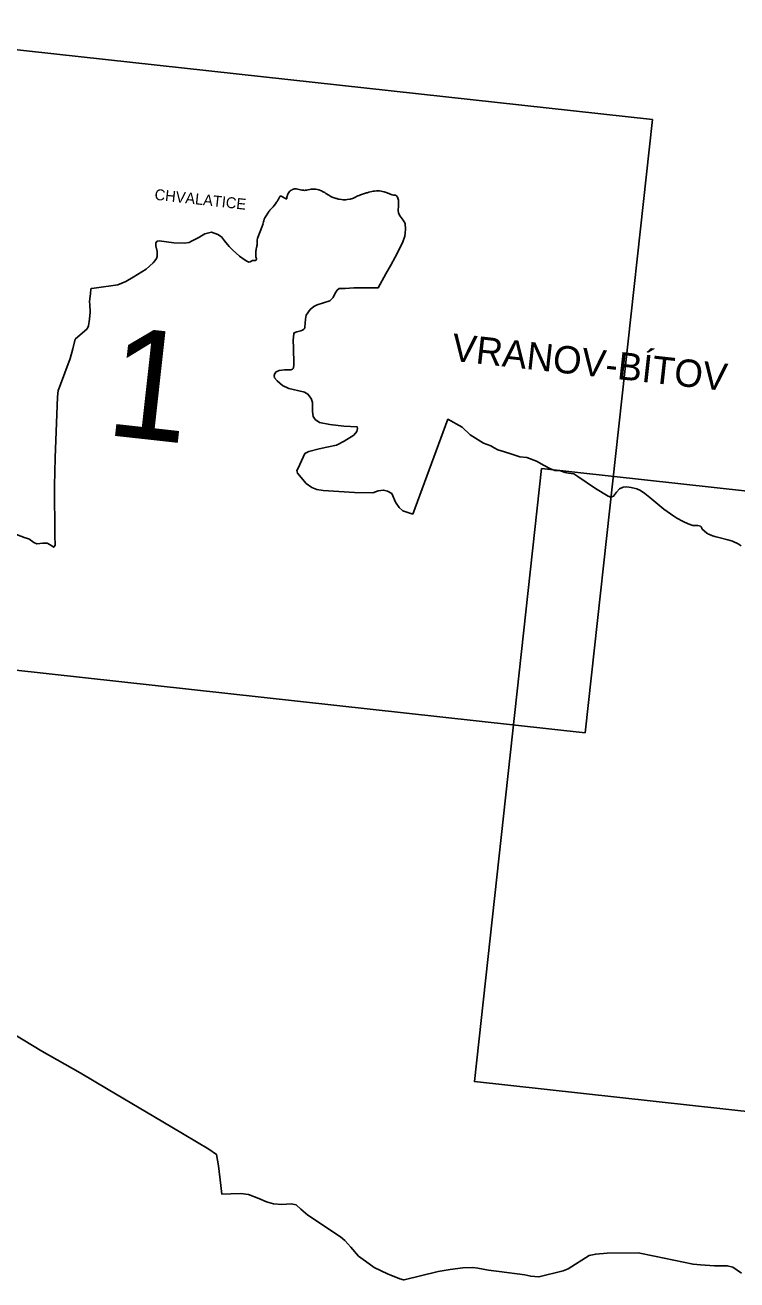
# Model space of a CAD drawing. Extents: x -678204 to -526855, y -1228851 to -1110393.
# Drawn here: x -663938 to -660037, y -1186114 to -1179242 of the extents above; entities that cross this region are included whole.
import ezdxf

# ---------------------------------------------------------------- set-up
doc = ezdxf.new("R2010")
doc.units = 0
for name, color, linetype in [('00_n_cyklo popisy detaily', 7, 'Continuous'), ('00_n_cyklo popisy ostatni', 7, 'Continuous'), ('00_n_cyklo prujezdne rekreacni hlavni', 7, 'Continuous'), ('00_n_cyklo prujezdne rekreacni vedlejsi', 7, 'Continuous'), ('00_n_cyklo studie rekreacni vedlejsi', 7, 'Continuous'), ('00_n_cyklo trasovani rekreacni hlavni', 7, 'Continuous'), ('00_n_cyklo trasovani rekreacni vedlejsi', 7, 'Continuous'), ('_HELP', 7, 'Continuous')]:
    doc.layers.add(name, color=color, linetype=linetype)

msp = doc.modelspace()

# ---------------------------------------------------------------- linework, layer by layer
at = {"layer": '00_n_cyklo prujezdne rekreacni hlavni'}
for points in [[(-664050.1, -1184736.6), (-663846.7, -1184860), (-663635.3, -1184980.1), (-663482.1, -1185070.9), (-663273, -1185195.5), (-663134.3, -1185277.8), (-662930.9, -1185398.4), (-662889.7, -1185426.6), (-662877.3, -1185489.2), (-662864.4, -1185596.3), (-662859.4, -1185644.8), (-662810.4, -1185642.9), (-662755, -1185640.9), (-662712.8, -1185645.5), (-662656.5, -1185667.7), (-662615.6, -1185686), (-662575.6, -1185697.3), (-662530.5, -1185700.2), (-662479.3, -1185697.6), (-662451.6, -1185702.8), (-662426.8, -1185727), (-662387.6, -1185758.2), (-662208.8, -1185878), (-662186, -1185898), (-662153.4, -1185935.1), (-662110, -1185984), (-662071.6, -1186010.5), (-662024.3, -1186045.2), (-661951.5, -1186079.4), (-661883.2, -1186107.1), (-661863.9, -1186113.5)], [(-661863.9, -1186113.5), (-661859.5, -1186112.5), (-661673.6, -1186068.1), (-661607.9, -1186056.2), (-661538, -1186047.5), (-661484.5, -1186046.5), (-661456.9, -1186048.5), (-661397.6, -1186059.7), (-661339.6, -1186067.5), (-661199.2, -1186085.5), (-661166.7, -1186093.9), (-661121.9, -1186097.5), (-660988.3, -1186063.7), (-660960.7, -1186052.4), (-660847.4, -1185980.2), (-660810.3, -1185972.3), (-660747.1, -1185967.2), (-660578.6, -1185966.1), (-660488.4, -1185983.6), (-660277.1, -1186028.1), (-660236.5, -1186031.5), (-660159.9, -1186036), (-660089.4, -1186036), (-660059.6, -1186043.4), (-660011.1, -1186077.2)]]:
    msp.add_lwpolyline(points, dxfattribs=at)
at = {"layer": '00_n_cyklo prujezdne rekreacni vedlejsi'}
for points in [[(-661812.1, -1181920.1), (-661867.4, -1181901.4), (-661887.9, -1181882.8), (-661907.9, -1181853.9), (-661927.1, -1181807.6), (-661951.6, -1181794.1), (-661973.4, -1181788.3), (-662002.3, -1181792.2), (-662031.9, -1181803.7), (-662132.8, -1181801.2), (-662305, -1181790.9), (-662338.4, -1181785.7), (-662366, -1181773.5), (-662396.9, -1181753), (-662444.4, -1181695.1), (-662448.3, -1181680.3), (-662440.6, -1181667.5), (-662403.9, -1181588.4), (-662382.1, -1181576.9), (-662325.5, -1181561.4), (-662283.8, -1181552.4), (-662231.7, -1181541.5), (-662188.7, -1181520.9), (-662135.3, -1181486.9), (-662119.9, -1181468.2), (-662115.4, -1181450.2), (-662118, -1181441.2), (-662190.6, -1181437.4), (-662267.1, -1181429), (-662324.3, -1181417.5), (-662347.4, -1181402.2), (-662359.6, -1181384.8), (-662363.5, -1181357.2), (-662362.2, -1181308.4), (-662369.2, -1181286.5), (-662387.9, -1181262.7), (-662407.1, -1181252.4), (-662413.6, -1181249.2), (-662493.3, -1181231.2), (-662528, -1181214.5), (-662556.9, -1181190.1), (-662570.1, -1181173), (-662572.3, -1181159.8), (-662569.4, -1181148.8), (-662562.4, -1181141.1), (-662545.5, -1181134.1), (-662516.8, -1181129.7), (-662482, -1181130), (-662472, -1181126.4), (-662467.6, -1181119.8), (-662465.1, -1181100.3), (-662466.3, -1181007), (-662469.2, -1180968.2), (-662467.4, -1180949.3), (-662465.9, -1180932.1), (-662462.5, -1180926.6), (-662449.5, -1180921.6), (-662426.2, -1180915.9), (-662418.1, -1180912.4), (-662411.1, -1180906.9), (-662404.4, -1180900.8), (-662404.2, -1180895.1), (-662401.6, -1180851.8), (-662396.8, -1180830.9), (-662374.8, -1180800), (-662355.3, -1180782.8), (-662336.6, -1180773.6), (-662268.2, -1180751), (-662249.6, -1180734.3), (-662238.7, -1180710.5), (-662227.8, -1180692.5), (-662216.5, -1180683.6), (-662183.1, -1180684.1), (-662136.8, -1180680.8), (-662015.9, -1180680.4), (-662002.7, -1180680.4), (-661960.4, -1180604), (-661933.8, -1180555.7), (-661910.5, -1180512.7), (-661869.5, -1180434.9), (-661856.6, -1180398.1), (-661854.3, -1180380.4), (-661853.7, -1180358.4), (-661854.8, -1180328.3), (-661866.1, -1180309.4), (-661883, -1180288.5), (-661892.1, -1180271.2), (-661893, -1180256.1), (-661891.8, -1180234), (-661892.1, -1180200.8), (-661897.5, -1180184.6), (-661901.5, -1180176.9), (-661905.7, -1180173.9)], [(-662692, -1180531.7), (-662695.8, -1180532.1), (-662704.2, -1180538.9), (-662710.9, -1180539.6), (-662722.5, -1180535.3), (-662742.3, -1180521), (-662762.3, -1180506.4), (-662797.2, -1180476.1), (-662818.6, -1180454.6), (-662844.7, -1180422.7), (-662862, -1180401.8), (-662881.6, -1180388.5), (-662915.5, -1180376.2), (-662952.5, -1180385.3), (-662990.2, -1180406.2), (-663025.2, -1180425.3), (-663039.2, -1180433), (-663066.2, -1180436.3), (-663123.1, -1180433.3), (-663202.6, -1180422.5), (-663214.1, -1180425.3), (-663221, -1180433.6), (-663220.7, -1180450.3), (-663214.3, -1180480.8), (-663213.8, -1180508.4), (-663217.7, -1180519.8), (-663226, -1180532.3), (-663236.3, -1180543.1), (-663274.2, -1180578.5), (-663346.4, -1180621.5), (-663385.8, -1180645.3), (-663429.2, -1180665), (-663558.9, -1180682.3), (-663575.7, -1180684.1), (-663578.3, -1180687.5), (-663579.8, -1180713.6), (-663583.8, -1180738.2), (-663585.2, -1180757.4), (-663583.1, -1180770.9), (-663581.2, -1180813.9), (-663585.3, -1180852.8), (-663590.2, -1180889.5), (-663598.1, -1180905.4), (-663663.1, -1180961.7), (-663675.9, -1181014.8), (-663691.2, -1181068), (-663749.4, -1181224.6), (-663755.8, -1181242), (-663759.7, -1181278), (-663772.3, -1181611.1), (-663776.6, -1181764.5), (-663774.6, -1182038.2), (-663773.9, -1182089), (-663780.5, -1182100.9), (-663801, -1182088.2), (-663816.7, -1182078.1), (-663840.3, -1182078.1), (-663874.1, -1182082.6), (-663889.8, -1182075.8), (-663916.8, -1182054.4), (-663937, -1182049.9), (-663985.4, -1182031.9)], [(-660227.8, -1182001.7), (-660228.5, -1181997), (-660231.8, -1181990.1), (-660236.9, -1181985), (-660251.1, -1181982.8), (-660278.6, -1181981.8), (-660303.7, -1181972.9), (-660330.7, -1181959.8), (-660366.2, -1181942.4), (-660382.8, -1181930.6), (-660436.6, -1181892.4), (-660513.4, -1181829.3), (-660540.8, -1181807.2), (-660564.6, -1181791), (-660586, -1181780.6), (-660615.9, -1181774.6), (-660639.2, -1181770.9), (-660660.3, -1181771.4), (-660680.2, -1181780.8), (-660696.9, -1181799), (-660712.6, -1181821.9), (-660728.2, -1181827.5), (-660743.2, -1181821.8), (-660812, -1181780.2), (-660909, -1181714), (-660930.9, -1181699.8), (-660959.8, -1181694.7), (-660977.5, -1181691.2), (-661003.4, -1181683.5), (-661035, -1181681.6), (-661061.9, -1181670.6), (-661093.2, -1181654), (-661134.4, -1181630), (-661188.3, -1181609.2), (-661226.5, -1181605.3), (-661271.2, -1181590.9), (-661311.2, -1181578.4), (-661347.4, -1181568), (-661367.3, -1181556.9), (-661384.5, -1181546.4), (-661425.8, -1181530.6), (-661498.1, -1181485.7), (-661543.1, -1181443.7), (-661620.8, -1181400.6), (-661812.1, -1181920.1)]]:
    msp.add_lwpolyline(points, dxfattribs=at)
at = {"layer": '00_n_cyklo studie rekreacni vedlejsi'}
for p, q in [((-662499.2, -1180170.4), (-662500.6, -1180174.2)), ((-662488.5, -1180153.7), (-662492.1, -1180158.1)), ((-662460.8, -1180138.5), (-662466.9, -1180140.1)), ((-662428.5, -1180143.5), (-662451.4, -1180138.4)), ((-662411.7, -1180146.3), (-662413.2, -1180146.1)), ((-662377.5, -1180141.5), (-662389.2, -1180144.6)), ((-662352, -1180140.1), (-662363.1, -1180139.8)), ((-662314.1, -1180149.5), (-662319.4, -1180147.2)), ((-662273.4, -1180173.6), (-662289, -1180163.1)), ((-662072.4, -1180162.7), (-662093.3, -1180169.5)), ((-662037.5, -1180153.2), (-662053.3, -1180157.2)), ((-662011.3, -1180149.5), (-662023.6, -1180150.8)), ((-661970.2, -1180155.3), (-661979.5, -1180152.5)), ((-661927, -1180170.8), (-661959.6, -1180158.8)), ((-661905.7, -1180173.9), (-661911.2, -1180173.8)), ((-662541, -1180180.7), (-662550.9, -1180197.8)), ((-662506.6, -1180193.4), (-662534.3, -1180178.8)), ((-662502.6, -1180183), (-662503.6, -1180191.9)), ((-662233.8, -1180190.7), (-662249.5, -1180185.4)), ((-662202.9, -1180196.9), (-662216.7, -1180194.9)), ((-662157, -1180194.3), (-662171.9, -1180196.8)), ((-662131.2, -1180185.4), (-662132.3, -1180186)), ((-662107.8, -1180174.8), (-662113.5, -1180177.1)), ((-662627, -1180304.6), (-662629.7, -1180313.5)), ((-662603.8, -1180265.8), (-662621, -1180291.8)), ((-662586.3, -1180245.1), (-662592.8, -1180251.9)), ((-662640.9, -1180348.9), (-662662.1, -1180404.9)), ((-662666.4, -1180433.9), (-662666.6, -1180441)), ((-662665.1, -1180417.9), (-662666, -1180427.1)), ((-662673.3, -1180487.3), (-662673.8, -1180504)), ((-662671.7, -1180516.3), (-662670, -1180520.4)), ((-662668.9, -1180459.8), (-662671, -1180469.1)), ((-662677.3, -1180531.4), (-662692, -1180531.7)), ((-660204.2, -1182021.9), (-660227.8, -1182001.7)), ((-660170.6, -1182038), (-660189.9, -1182030.4)), ((-660085.9, -1182060), (-660143.9, -1182046.3)), ((-660036.7, -1182078.8), (-660037.9, -1182078.2))]:
    msp.add_line(p, q, dxfattribs=at)
for centre, radius, start, end in [((-662462.9, -1180187.6), 40, 160.33333, 173.42013), ((-662461.5, -1180183.8), 40, 139.90308, 160.33333), ((-662457.9, -1180179.5), 40, 122.79014, 139.90308), ((-662456.8, -1180178.8), 40, 104.58657, 122.79014), ((-662455.7, -1180157.9), 20, 77.38567, 104.58657), ((-662395.7, -1179997.1), 150, 257.38567, 263.31699), ((-662404.8, -1180086.7), 60, 263.31699, 285.02658), ((-662364.5, -1180189.8), 50, 88.3446, 105.02658), ((-662354.6, -1180230.1), 90, 66.9806, 88.3446), ((-662372.7, -1180287.6), 150, 56.05492, 66.9806), ((-662217.5, -1180090.7), 100, 236.05492, 251.36339), ((-662031.7, -1180359.8), 200, 107.9257, 112.34408), ((-661980, -1180448.1), 300, 104.13058, 107.9257), ((-662013.1, -1180250.2), 100, 96.064, 104.13058), ((-662002.8, -1180229), 80, 73.08726, 96.064), ((-662028.3, -1180346.7), 200, 69.9027, 73.08726), ((-661909.8, -1180123.8), 50, 249.9027, 268.49392), ((-662767.4, -1180072.8), 250, 316.43223, 326.16198), ((-662767.2, -1180072.5), 250, 326.16198, 329.92449), ((-662536.6, -1180183.2), 5, 62.13845, 149.92449), ((-662505.6, -1180191.7), 2, 242.13845, 353.42013), ((-662201.8, -1180096), 100, 251.36339, 261.43582), ((-662188, -1180098.1), 100, 261.43582, 279.24776), ((-662169.8, -1180115.4), 80, 279.24776, 297.94511), ((-662037.5, -1180362.1), 200, 112.34408, 117.94511), ((-662579.2, -1180319.3), 50, 146.61999, 162.82175), ((-662520.3, -1180320.9), 100, 136.43223, 146.61999), ((-662874.7, -1180260.4), 250, 339.25816, 344.34226), ((-662152.1, -1180461.2), 500, 162.82175, 164.34226), ((-662766.6, -1180438.3), 100, 347.52881, 358.4293), ((-662566.4, -1180436.6), 100, 174.5327, 178.4293), ((-662615.3, -1180422.6), 50, 159.25816, 174.5327), ((-662643.9, -1180505), 30, 178.0284, 201.96177), ((-662573.3, -1180490.7), 100, 167.52881, 178.0284), ((-662677.4, -1180523.4), 8, 271.2676, 21.96177), ((-660171.7, -1181983.9), 50, 229.56013, 248.65897), ((-660097.8, -1181851.7), 200, 248.65897, 256.68492), ((-660132, -1182254.7), 200, 61.9425, 76.68492), ((-660130.8, -1182255.3), 200, 53.83808, 61.9425)]:
    msp.add_arc(centre, radius, start, end, dxfattribs=at)
at = {"layer": '00_n_cyklo trasovani rekreacni hlavni'}
for points in [[(-664050.1, -1184736.6), (-663846.7, -1184860), (-663635.3, -1184980.1), (-663482.1, -1185070.9), (-663273, -1185195.5), (-663134.3, -1185277.8), (-662930.9, -1185398.4), (-662889.7, -1185426.6), (-662877.3, -1185489.2), (-662864.4, -1185596.3), (-662859.4, -1185644.8), (-662810.4, -1185642.9), (-662755, -1185640.9), (-662712.8, -1185645.5), (-662656.5, -1185667.7), (-662615.6, -1185686), (-662575.6, -1185697.3), (-662530.5, -1185700.2), (-662479.3, -1185697.6), (-662451.6, -1185702.8), (-662426.8, -1185727), (-662387.6, -1185758.2), (-662208.8, -1185878), (-662186, -1185898), (-662153.4, -1185935.1), (-662110, -1185984), (-662071.6, -1186010.5), (-662024.3, -1186045.2), (-661951.5, -1186079.4), (-661883.2, -1186107.1), (-661863.9, -1186113.5)], [(-661863.9, -1186113.5), (-661859.5, -1186112.5), (-661673.6, -1186068.1), (-661607.9, -1186056.2), (-661538, -1186047.5), (-661484.5, -1186046.5), (-661456.9, -1186048.5), (-661397.6, -1186059.7), (-661339.6, -1186067.5), (-661199.2, -1186085.5), (-661166.7, -1186093.9), (-661121.9, -1186097.5), (-660988.3, -1186063.7), (-660960.7, -1186052.4), (-660847.4, -1185980.2), (-660810.3, -1185972.3), (-660747.1, -1185967.2), (-660578.6, -1185966.1), (-660488.4, -1185983.6), (-660277.1, -1186028.1), (-660236.5, -1186031.5), (-660159.9, -1186036), (-660089.4, -1186036), (-660059.6, -1186043.4), (-660011.1, -1186077.2)]]:
    msp.add_lwpolyline(points, dxfattribs=at)
at = {"layer": '00_n_cyklo trasovani rekreacni vedlejsi'}
for p, q in [((-662499.2, -1180170.4), (-662500.6, -1180174.2)), ((-662488.5, -1180153.7), (-662492.1, -1180158.1)), ((-662460.8, -1180138.5), (-662466.9, -1180140.1)), ((-662428.5, -1180143.5), (-662451.4, -1180138.4)), ((-662411.7, -1180146.3), (-662413.2, -1180146.1)), ((-662377.5, -1180141.5), (-662389.2, -1180144.6)), ((-662352, -1180140.1), (-662363.1, -1180139.8)), ((-662314.1, -1180149.5), (-662319.4, -1180147.2)), ((-662273.4, -1180173.6), (-662289, -1180163.1)), ((-662072.4, -1180162.7), (-662093.3, -1180169.5)), ((-662037.5, -1180153.2), (-662053.3, -1180157.2)), ((-662011.3, -1180149.5), (-662023.6, -1180150.8)), ((-661970.2, -1180155.3), (-661979.5, -1180152.5)), ((-661927, -1180170.8), (-661959.6, -1180158.8)), ((-661905.7, -1180173.9), (-661911.2, -1180173.8)), ((-662541, -1180180.7), (-662550.9, -1180197.8)), ((-662506.6, -1180193.4), (-662534.3, -1180178.8)), ((-662502.6, -1180183), (-662503.6, -1180191.9)), ((-662233.8, -1180190.7), (-662249.5, -1180185.4)), ((-662202.9, -1180196.9), (-662216.7, -1180194.9)), ((-662157, -1180194.3), (-662171.9, -1180196.8)), ((-662131.2, -1180185.4), (-662132.3, -1180186)), ((-662107.8, -1180174.8), (-662113.5, -1180177.1)), ((-662627, -1180304.6), (-662629.7, -1180313.5)), ((-662603.8, -1180265.8), (-662621, -1180291.8)), ((-662586.3, -1180245.1), (-662592.8, -1180251.9)), ((-662640.9, -1180348.9), (-662662.1, -1180404.9)), ((-662666.4, -1180433.9), (-662666.6, -1180441)), ((-662665.1, -1180417.9), (-662666, -1180427.1)), ((-662673.3, -1180487.3), (-662673.8, -1180504)), ((-662671.7, -1180516.3), (-662670, -1180520.4)), ((-662668.9, -1180459.8), (-662671, -1180469.1)), ((-662677.3, -1180531.4), (-662692, -1180531.7)), ((-660204.2, -1182021.9), (-660227.8, -1182001.7)), ((-660170.6, -1182038), (-660189.9, -1182030.4)), ((-660085.9, -1182060), (-660143.9, -1182046.3)), ((-660036.7, -1182078.8), (-660037.9, -1182078.2))]:
    msp.add_line(p, q, dxfattribs=at)
for points in [[(-661812.1, -1181920.1), (-661867.4, -1181901.4), (-661887.9, -1181882.8), (-661907.9, -1181853.9), (-661927.1, -1181807.6), (-661951.6, -1181794.1), (-661973.4, -1181788.3), (-662002.3, -1181792.2), (-662031.9, -1181803.7), (-662132.8, -1181801.2), (-662305, -1181790.9), (-662338.4, -1181785.7), (-662366, -1181773.5), (-662396.9, -1181753), (-662444.4, -1181695.1), (-662448.3, -1181680.3), (-662440.6, -1181667.5), (-662403.9, -1181588.4), (-662382.1, -1181576.9), (-662325.5, -1181561.4), (-662283.8, -1181552.4), (-662231.7, -1181541.5), (-662188.7, -1181520.9), (-662135.3, -1181486.9), (-662119.9, -1181468.2), (-662115.4, -1181450.2), (-662118, -1181441.2), (-662190.6, -1181437.4), (-662267.1, -1181429), (-662324.3, -1181417.5), (-662347.4, -1181402.2), (-662359.6, -1181384.8), (-662363.5, -1181357.2), (-662362.2, -1181308.4), (-662369.2, -1181286.5), (-662387.9, -1181262.7), (-662407.1, -1181252.4), (-662413.6, -1181249.2), (-662493.3, -1181231.2), (-662528, -1181214.5), (-662556.9, -1181190.1), (-662570.1, -1181173), (-662572.3, -1181159.8), (-662569.4, -1181148.8), (-662562.4, -1181141.1), (-662545.5, -1181134.1), (-662516.8, -1181129.7), (-662482, -1181130), (-662472, -1181126.4), (-662467.6, -1181119.8), (-662465.1, -1181100.3), (-662466.3, -1181007), (-662469.2, -1180968.2), (-662467.4, -1180949.3), (-662465.9, -1180932.1), (-662462.5, -1180926.6), (-662449.5, -1180921.6), (-662426.2, -1180915.9), (-662418.1, -1180912.4), (-662411.1, -1180906.9), (-662404.4, -1180900.8), (-662404.2, -1180895.1), (-662401.6, -1180851.8), (-662396.8, -1180830.9), (-662374.8, -1180800), (-662355.3, -1180782.8), (-662336.6, -1180773.6), (-662268.2, -1180751), (-662249.6, -1180734.3), (-662238.7, -1180710.5), (-662227.8, -1180692.5), (-662216.5, -1180683.6), (-662183.1, -1180684.1), (-662136.8, -1180680.8), (-662015.9, -1180680.4), (-662002.7, -1180680.4), (-661960.4, -1180604), (-661933.8, -1180555.7), (-661910.5, -1180512.7), (-661869.5, -1180434.9), (-661856.6, -1180398.1), (-661854.3, -1180380.4), (-661853.7, -1180358.4), (-661854.8, -1180328.3), (-661866.1, -1180309.4), (-661883, -1180288.5), (-661892.1, -1180271.2), (-661893, -1180256.1), (-661891.8, -1180234), (-661892.1, -1180200.8), (-661897.5, -1180184.6), (-661901.5, -1180176.9), (-661905.7, -1180173.9)], [(-662692, -1180531.7), (-662695.8, -1180532.1), (-662704.2, -1180538.9), (-662710.9, -1180539.6), (-662722.5, -1180535.3), (-662742.3, -1180521), (-662762.3, -1180506.4), (-662797.2, -1180476.1), (-662818.6, -1180454.6), (-662844.7, -1180422.7), (-662862, -1180401.8), (-662881.6, -1180388.5), (-662915.5, -1180376.2), (-662952.5, -1180385.3), (-662990.2, -1180406.2), (-663025.2, -1180425.3), (-663039.2, -1180433), (-663066.2, -1180436.3), (-663123.1, -1180433.3), (-663202.6, -1180422.5), (-663214.1, -1180425.3), (-663221, -1180433.6), (-663220.7, -1180450.3), (-663214.3, -1180480.8), (-663213.8, -1180508.4), (-663217.7, -1180519.8), (-663226, -1180532.3), (-663236.3, -1180543.1), (-663274.2, -1180578.5), (-663346.4, -1180621.5), (-663385.8, -1180645.3), (-663429.2, -1180665), (-663558.9, -1180682.3), (-663575.7, -1180684.1), (-663578.3, -1180687.5), (-663579.8, -1180713.6), (-663583.8, -1180738.2), (-663585.2, -1180757.4), (-663583.1, -1180770.9), (-663581.2, -1180813.9), (-663585.3, -1180852.8), (-663590.2, -1180889.5), (-663598.1, -1180905.4), (-663663.1, -1180961.7), (-663675.9, -1181014.8), (-663691.2, -1181068), (-663749.4, -1181224.6), (-663755.8, -1181242), (-663759.7, -1181278), (-663772.3, -1181611.1), (-663776.6, -1181764.5), (-663774.6, -1182038.2), (-663773.9, -1182089), (-663780.5, -1182100.9), (-663801, -1182088.2), (-663816.7, -1182078.1), (-663840.3, -1182078.1), (-663874.1, -1182082.6), (-663889.8, -1182075.8), (-663916.8, -1182054.4), (-663937, -1182049.9), (-663985.4, -1182031.9)], [(-660227.8, -1182001.7), (-660228.5, -1181997), (-660231.8, -1181990.1), (-660236.9, -1181985), (-660251.1, -1181982.8), (-660278.6, -1181981.8), (-660303.7, -1181972.9), (-660330.7, -1181959.8), (-660366.2, -1181942.4), (-660382.8, -1181930.6), (-660436.6, -1181892.4), (-660513.4, -1181829.3), (-660540.8, -1181807.2), (-660564.6, -1181791), (-660586, -1181780.6), (-660615.9, -1181774.6), (-660639.2, -1181770.9), (-660660.3, -1181771.4), (-660680.2, -1181780.8), (-660696.9, -1181799), (-660712.6, -1181821.9), (-660728.2, -1181827.5), (-660743.2, -1181821.8), (-660812, -1181780.2), (-660909, -1181714), (-660930.9, -1181699.8), (-660959.8, -1181694.7), (-660977.5, -1181691.2), (-661003.4, -1181683.5), (-661035, -1181681.6), (-661061.9, -1181670.6), (-661093.2, -1181654), (-661134.4, -1181630), (-661188.3, -1181609.2), (-661226.5, -1181605.3), (-661271.2, -1181590.9), (-661311.2, -1181578.4), (-661347.4, -1181568), (-661367.3, -1181556.9), (-661384.5, -1181546.4), (-661425.8, -1181530.6), (-661498.1, -1181485.7), (-661543.1, -1181443.7), (-661620.8, -1181400.6), (-661812.1, -1181920.1)]]:
    msp.add_lwpolyline(points, dxfattribs=at)
for centre, radius, start, end in [((-662462.9, -1180187.6), 40, 160.33333, 173.42013), ((-662461.5, -1180183.8), 40, 139.90308, 160.33333), ((-662457.9, -1180179.5), 40, 122.79014, 139.90308), ((-662456.8, -1180178.8), 40, 104.58657, 122.79014), ((-662455.7, -1180157.9), 20, 77.38567, 104.58657), ((-662395.7, -1179997.1), 150, 257.38567, 263.31699), ((-662404.8, -1180086.7), 60, 263.31699, 285.02658), ((-662364.5, -1180189.8), 50, 88.3446, 105.02658), ((-662354.6, -1180230.1), 90, 66.9806, 88.3446), ((-662372.7, -1180287.6), 150, 56.05492, 66.9806), ((-662217.5, -1180090.7), 100, 236.05492, 251.36339), ((-662031.7, -1180359.8), 200, 107.9257, 112.34408), ((-661980, -1180448.1), 300, 104.13058, 107.9257), ((-662013.1, -1180250.2), 100, 96.064, 104.13058), ((-662002.8, -1180229), 80, 73.08726, 96.064), ((-662028.3, -1180346.7), 200, 69.9027, 73.08726), ((-661909.8, -1180123.8), 50, 249.9027, 268.49392), ((-662767.4, -1180072.8), 250, 316.43223, 326.16198), ((-662767.2, -1180072.5), 250, 326.16198, 329.92449), ((-662536.6, -1180183.2), 5, 62.13845, 149.92449), ((-662505.6, -1180191.7), 2, 242.13845, 353.42013), ((-662201.8, -1180096), 100, 251.36339, 261.43582), ((-662188, -1180098.1), 100, 261.43582, 279.24776), ((-662169.8, -1180115.4), 80, 279.24776, 297.94511), ((-662037.5, -1180362.1), 200, 112.34408, 117.94511), ((-662579.2, -1180319.3), 50, 146.61999, 162.82175), ((-662520.3, -1180320.9), 100, 136.43223, 146.61999), ((-662874.7, -1180260.4), 250, 339.25816, 344.34226), ((-662152.1, -1180461.2), 500, 162.82175, 164.34226), ((-662766.6, -1180438.3), 100, 347.52881, 358.4293), ((-662566.4, -1180436.6), 100, 174.5327, 178.4293), ((-662615.3, -1180422.6), 50, 159.25816, 174.5327), ((-662643.9, -1180505), 30, 178.0284, 201.96177), ((-662573.3, -1180490.7), 100, 167.52881, 178.0284), ((-662677.4, -1180523.4), 8, 271.2676, 21.96177), ((-660171.7, -1181983.9), 50, 229.56013, 248.65897), ((-660097.8, -1181851.7), 200, 248.65897, 256.68492), ((-660132, -1182254.7), 200, 61.9425, 76.68492), ((-660130.8, -1182255.3), 200, 53.83808, 61.9425)]:
    msp.add_arc(centre, radius, start, end, dxfattribs=at)
at = {"layer": '_HELP'}
for points in [[(-665214.8, -1179241.7), (-660500.2, -1179759.4), (-660868.9, -1183116.9), (-665583.5, -1182599.2)], [(-661107, -1181669.8), (-656392.4, -1182187.5), (-656761.1, -1185545), (-661475.7, -1185027.3)]]:
    msp.add_lwpolyline(points, close=True, dxfattribs=at)

# ---------------------------------------------------------------- texts
at = {"layer": '00_n_cyklo popisy detaily'}
msp.add_text('CHVALATICE', height=60, rotation=353.68355, dxfattribs=at).set_placement((-663230.5, -1180197.9))
at = {"layer": '00_n_cyklo popisy ostatni'}
msp.add_text('VRANOV-BÍTOV', height=150, rotation=353.68355, dxfattribs=at).set_placement((-661605.3, -1181079.2))
at = {"layer": '_HELP'}
msp.add_text('1', height=600, rotation=353.68355, dxfattribs=at).set_placement((-663505.6, -1181484.7))

doc.saveas('drawing.dxf')
